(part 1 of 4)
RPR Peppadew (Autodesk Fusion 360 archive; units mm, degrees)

design "servo flipper v2" references "RPR 2A5V Booster", "Flysky FS-iA6 Receiver"
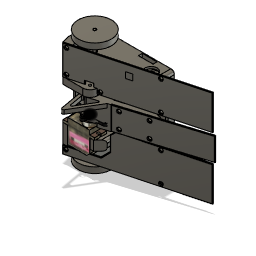
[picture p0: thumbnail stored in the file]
parameter "TrayGap" = 0.2
parameter "TraySideWidth" = 3
parameter "TrayEndExtraMinus1" = 0.8 (= "1 mm - TrayGap")
parameter "d525" = 1
parameter "d1064" = 6.3053
parameter "d551" = -47.5
parameter "d552" = 0
parameter "d553" = -47.5
parameter "d554" = 0
parameter "d555" = -19.75
parameter "d556" = 0
parameter "d557" = -19.75
parameter "d558" = 0
parameter "d559" = 5
parameter "d560" = 0
parameter "d561" = 3
parameter "d562" = 0
parameter "d563" = -8
parameter "d564" = 0
parameter "d565" = -4
parameter "d566" = 0
parameter "d567" = 0.3
parameter "d570" = 0.5
parameter "d571" = 0
parameter "d572" = 0.5
parameter "d573" = 0
parameter "d576" = 80
parameter "d577" = 0
parameter "d578" = 13
parameter "d579" = 0
parameter "d580" = 80
parameter "d581" = 0
parameter "d582" = 13
parameter "d583" = 0
parameter "d584" = 0.001
parameter "d585" = 0
parameter "d588" = -0.001
parameter "d589" = 0
parameter "d590" = 0.283
parameter "d591" = 0
parameter "d592" = -3.999
parameter "d593" = 0
parameter "d595" = 30
parameter "d597" = 30
parameter "d603" = 39.501
parameter "d604" = 0
parameter "d606" = 10
parameter "d607" = 0.5
parameter "d608" = 45
parameter "d611" = -47.5
parameter "d612" = 0
parameter "d613" = -47.5
parameter "d614" = 0
parameter "d615" = 1
parameter "d616" = 0
parameter "d618" = 2
parameter "d619" = 0
parameter "d622" = 2
parameter "d627" = -4
parameter "d628" = 0
parameter "d629" = -3.999
parameter "d630" = 0
place_component Diameter Dimension-2 3.2 Radial Dimension-2 1 Diameter Dimension-2 3.2 Diameter Dimension-3 3.2 Diameter Dimension-2 3 Diameter Dimension-3 7 Diameter Dimension-4 3 Diameter Dimension-5 7 Linear Dimension-2 -3 Linear Dimension-2 1 Linear Dimension-3 45 Linear Dimension-2 -2 Diameter Dimension-2 4 Diameter Dimension-3 4 Radial Dimension-2 4 Linear Dimension-2 10 Linear Dimension-3 15
base_feature "Base Feature1"
base_feature "Base Feature1"
joint "Assemble2" alignAngle -180 alignOffsetX 0 alignOffsetY 0 alignOffsetZ 0 TaperAngle 0
sketch "Sketch2" plane through (0, 6.1985, 0) normal (0, 1, 0) x axis (-1, 0, 0)
  curve K1 (0, 1.25) -> (-1, 0.7813)
  line L1 (-1, -0.8816) -> (-1, 0.7813)
  curve K2 (-1, -0.8816) -> (0, -1.3507)
  curve K3 (0, -1.3507) -> (0, 1.25)
  line L2 (-13.7, -73.6015) -> (-13.7, -30.0015)
  line L3 (-9, -73.6015) -> (-13.7, -73.6015)
  line L4 (-9, -39.8015) -> (-9, -73.6015)
  line L5 (14.2, -39.8015) -> (-9, -39.8015)
  line L6 (14.2, -33.0015) -> (14.2, -39.8015)
  line L7 (-9, -33.0015) -> (14.2, -33.0015)
  line L8 (-9, -30.0015) -> (-9, -33.0015)
  line L9 (-13.7, -30.0015) -> (-9, -30.0015)
  line L10 (-13.7, -39.8015) -> (14.2, -39.8015)
  line L11 (-13.7, -30.0015) -> (-13.7, -39.8015)
  line L12 (14.2, -30.0015) -> (-13.7, -30.0015)
  line L13 (14.2, -39.8015) -> (14.2, -30.0015)
  circle C1 centre (0, 0) radius 17
  circle C2 centre (0, 0) radius 1.5
  point P1 (0, 0)
  point P2 (0, 0)
  coincident P1 P2
  concentric C1 C2
  dimension "d12" diameter C1 = 34
  dimension "d13" diameter C2 = 3
extrude "Extrude2" new body sketch "Sketch2" profile of C1 C2 against normal blind 6
extrude "Extrude3" cut of existing geometry blind -0.25
extrude "Extrude4" cut of existing geometry blind -0.25
offset_faces "OffsetFaces1" distance -0.5
sketch "Sketch3" plane through (0, -3.0015, 0) normal (0, 1, 0) x axis (-1, 0, 0)
  line L1 (6.05, -5.05) -> (6.05, 5)
  line L2 (-6.05, -5.05) -> (6.05, -5.05)
  line L3 (-6.05, 5) -> (-6.05, -5.05)
  line L4 (-9, 5) -> (-6.05, 5)
  line L5 (-9, -8) -> (-9, 5)
  line L6 (9, -8) -> (-9, -8)
  line L7 (9, 5) -> (9, -8)
  line L8 (6.05, 5) -> (9, 5)
  curve K1 (0, 1.25) -> (-1, 0.7813)
  line L9 (-1, -0.8816) -> (-1, 0.7813)
  curve K2 (-1, -0.8816) -> (0, -1.3507)
  curve K3 (0, -1.3507) -> (0, 1.25)
  line L10 (-3, 6.4529) -> (3, 6.4529)
  line L11 (-3, -6.4529) -> (-3, 6.4529)
  line L12 (3, -6.4529) -> (-3, -6.4529)
  line L13 (3, 6.4529) -> (3, -6.4529)
  line L14 (-3, -6.4529) -> (3, 6.4529)
  line L15 (3, -6.4529) -> (-3, 6.4529)
  line L16 (9, 5) -> (-9, 5)
  line L17 (9, -8) -> (9, 5)
  line L18 (-9, -8) -> (9, -8)
  line L19 (-9, 5) -> (-9, -8)
  circle C1 centre (0, 0) radius 3
  point P1 (0, 0)
  point P14 (0, 0)
  point P19 (0, 0)
  point P8 (9, -8)
  point P22 (9, -8)
  point P6 (-9, 5)
  point P20 (-9, 5)
  point P17 (-3, -6.4529)
  point P18 (3, -6.4529)
  coincident P1 P14
  horizontal L10
  perpendicular L10 L11
  parallel L10 L12
  parallel L11 L13
  coincident L14 P19
  coincident L15 P19
  coincident P1 P19
  horizontal L16
  vertical L17
  horizontal L18
  vertical L19
  coincident P8 P22
  coincident P6 P20
  dimension "d21" diameter C1 = 6
  dimension "d22" distance P17 P18 = 6
extrude "Extrude5" add sketch "Sketch3" profile of L1 L2 L3 L4 L5 L6 L7 L8 C1 L11 L12 L13 L16 L17 L18 L19 along normal blind 0.8
base_feature "Base Feature1" AlongDistance -0.001 TaperAngle 0
place_component sketch "Sketch163"
base_feature "Base Feature1" sketch "Sketch163"
joint "Assemble2" alignAngle -180 named "d8_1" alignOffsetX 0 named "d9_1" alignOffsetY 0 named "d10_1" alignOffsetZ 0 named "d11_1"
sketch "Sketch2" plane through (0, 6.1985, 0) normal (0, 1, 0) x axis (-1, 0, 0)
  curve K1 (0, 1.25) -> (-1, 0.7813)
  line L1 (-1, -0.8816) -> (-1, 0.7813)
  curve K2 (-1, -0.8816) -> (0, -1.3507)
  curve K3 (0, -1.3507) -> (0, 1.25)
  circle C1 centre (0, 0) radius 17
  circle C2 centre (0, 0) radius 1.5
  point P1 (0, 0)
  point P2 (0, 0)
  coincident P1 P2
  concentric C1 C2
  dimension "d12_1" diameter C1 = 34
  dimension "d13_1" diameter C2 = 3
extrude "Extrude2" new body sketch "Sketch2" profile of C1 C2 against normal blind 6 named "d14_1"
extrude "Extrude3" cut of existing geometry blind -0.25 named "d16_1"
extrude "Extrude4" cut of existing geometry blind -0.25 named "d18_1"
offset_faces "OffsetFaces1" distance -0.5 named "d20_1"
sketch "Sketch3" plane through (0, -3.0015, 0) normal (0, 1, 0) x axis (-1, 0, 0)
  line L1 (6.05, -5.05) -> (6.05, 5)
  line L2 (-6.05, -5.05) -> (6.05, -5.05)
  line L3 (-6.05, 5) -> (-6.05, -5.05)
  line L4 (-9, 5) -> (-6.05, 5)
  line L5 (-9, -8) -> (-9, 5)
  line L6 (9, -8) -> (-9, -8)
  line L7 (9, 5) -> (9, -8)
  line L8 (6.05, 5) -> (9, 5)
  curve K1 (0, 1.25) -> (-1, 0.7813)
  line L9 (-1, -0.8816) -> (-1, 0.7813)
  curve K2 (-1, -0.8816) -> (0, -1.3507)
  curve K3 (0, -1.3507) -> (0, 1.25)
  line L10 (-3, 6.4529) -> (3, 6.4529)
  line L11 (-3, -6.4529) -> (-3, 6.4529)
  line L12 (3, -6.4529) -> (-3, -6.4529)
  line L13 (3, 6.4529) -> (3, -6.4529)
  line L14 (-3, -6.4529) -> (3, 6.4529)
  line L15 (3, -6.4529) -> (-3, 6.4529)
  line L16 (9, 5) -> (-9, 5)
  line L17 (9, -8) -> (9, 5)
  line L18 (-9, -8) -> (9, -8)
  line L19 (-9, 5) -> (-9, -8)
  circle C1 centre (0, 0) radius 3
  point P1 (0, 0)
  point P14 (0, 0)
  point P19 (0, 0)
  point P8 (9, -8)
  point P22 (9, -8)
  point P6 (-9, 5)
  point P20 (-9, 5)
  point P17 (-3, -6.4529)
  point P18 (3, -6.4529)
  coincident P1 P14
  horizontal L10
  perpendicular L10 L11
  parallel L10 L12
  parallel L11 L13
  coincident L14 P19
  coincident L15 P19
  coincident P1 P19
  horizontal L16
  vertical L17
  horizontal L18
  vertical L19
  coincident P8 P22
  coincident P6 P20
  dimension "d21_1" diameter C1 = 6
  dimension "d22_1" distance P17 P18 = 6
extrude "Extrude5" add sketch "Sketch3" profile of L1 L2 L3 L4 L5 L6 L7 L8 C1 L11 L12 L13 L16 L17 L18 L19 along normal blind 0.8 named "d23_1"
joint "Assemble1" alignAngle 180 alignOffsetX 0 alignOffsetY 0 alignOffsetZ 40
sketch "Shaft" plane through (0, 0, 0) normal (0, 1, 0) x axis (1, 0, 0)
  line L1 (0, 2.4) -> (0, 0)
  line L2 (-0.7416, 2.2825) -> (0, 0)
  line L3 (0, 2.25) -> (-0.6953, 2.1399)
  line L4 (-0.3754, 2.3705) -> (-0.3476, 2.1949)
  line L5 (-4, 2.4) -> (0, 2.4)
  line L6 (-1.5372, 2.0346) -> (-0.352, 2.2223)
  curve K1 (-0.352, 2.2223) -> (0, 2.4)
  curve K2 (-0.0471, 2.4) -> (0.0471, 2.4)
  curve K3 (-0.3985, 2.2149) -> (-0.3054, 2.2297)
  curve K4 (0.352, 2.2223) -> (0, 2.4)
  curve K5 (0.0471, 2.4) -> (-0.0471, 2.4)
  curve K6 (0.3985, 2.2149) -> (0.3054, 2.2297)
  line L7 (0, 0) -> (0.352, 2.2223)
  line L8 (0, 0) -> (-0.352, 2.2223)
  curve K7 (-0.352, 2.2223) -> (-0.7416, 2.2825)
  curve K8 (-0.6968, 2.2971) -> (-0.7865, 2.268)
  curve K9 (-0.3054, 2.2297) -> (-0.3985, 2.2149)
  circle C1 centre (0, 0) radius 1
  circle C2 centre (0, 0) radius 2.4
  circle C3 centre (0, 0) radius 2.25
  circle C4 centre (0, 0) radius 1.625
  point P1 (0, 0)
  point P2 (0, 0)
  point P5 (0, 0)
  point P6 (0, 2.4)
  point P11 (0, 0)
  point P7 (-0.7416, 2.2825)
  point P12 (-0.7416, 2.2825)
  point P13 (-0.6953, 2.1399)
  point P14 (0, 2.25)
  point P15 (-0.3476, 2.1949)
  point P31 (-0.3476, 2.1949)
  point P32 (-0.3754, 2.3705)
  point P34 (-0.352, 2.2223)
  point P40 (0, 2.4)
  point P41 (0.352, 2.2223)
  point P36 (0.0471, 2.4)
  point P42 (-0.0471, 2.4)
  point P37 (-0.0471, 2.4)
  point P43 (0.0471, 2.4)
  point P38 (-0.3054, 2.2297)
  point P44 (0.3054, 2.2297)
  point P39 (-0.3985, 2.2149)
  point P45 (0.3985, 2.2149)
  point P4 (0, 0)
  point P46 (0, 0)
  point P48 (-0.7416, 2.2825)
  point P49 (-0.352, 2.2223)
  point P50 (-0.7865, 2.268)
  point P51 (-0.6968, 2.2971)
  point P52 (-0.3985, 2.2149)
  point P53 (-0.3054, 2.2297)
  point P33 (-4, 2.4)
  point P35 (-1.5372, 2.0346)
  coincident P1 P2
  concentric C1 C2
  concentric C1 C3
  coincident P1 P5
  coincident C2 P6
  vertical L1
  coincident P2 P11
  coincident P7 P12
  coincident C3 P13
  coincident L2 P13
  coincident C3 P14
  coincident L1 P14
  midpoint L3 P15
  coincident P15 P31
  coincident C2 P32
  perpendicular L3 L4
  tangent C2 L5
  coincident C3 P34
  coincident L4 P34
  perpendicular L4 L6
  midpoint P6 K2
  parallel L5 K2
  midpoint P34 K3
  parallel L6 K3
  symmetric P6 L1 P40
  symmetric L1 P34 P41
  symmetric L1 P36 P42
  symmetric L1 P37 P43
  symmetric L1 P38 P44
  symmetric L1 P39 P45
  coincident P4 P46
  concentric C2 C4
  symmetric P6 L4 P48
  symmetric L4 P34 P49
  symmetric L4 P36 P50
  symmetric L4 P37 P51
  symmetric L4 P38 P52
  symmetric L4 P39 P53
  dimension "ScrewholeDia" diameter C1 = 2
  dimension "ShaftOuterDia" diameter C2 = 4.8
  dimension "ShaftSplinesInnerDia" diameter C3 = 4.5
  dimension "d6" distance P6 P33 = 4
  dimension "d7" distance P34 P35 = 1.2 (= "ShaftOuterDia / 4")
  dimension "SplineTipPointiness" distance P36 P37 = 0.0942 (= "ShaftOuterDia * PI / NumSplines / 8")
  dimension "SplineInnerPointiness" distance P38 P39 = 0.0942 (= "ShaftOuterDia * PI / NumSplines / 8")
  dimension "d13_2" diameter C4 = 3.25 (= "ScrewholeDia + 0.5 * ( ( ShaftSplinesInnerDia - ScrewholeDia ) )")
  dimension "d5" C-Pattern1-Angle = 360
  dimension "ServoTrayThickness" AlongDistance = 3
extrude "Extrude3" new body sketch "Shaft" profile of C1 C2 K1 K4 L7 L8 C4 no distance stored bodies "Shaft"
extrude "Extrude4" cut sketch "Shaft" profile of C1 C2 K1 L7 L8 K7 no distance stored
circular_pattern "C-Pattern3" TotalAngle 360
extrude "Extrude1" new body sketch "Shaft" profile of C1 K1 K4 L7 L8 C4 along normal blind 3.5 named "ShaftHeight" bodies "Ignore"
coil_primitive "CoilPrimitive1" Diameter 2 (= "ScrewholeDia") SectionSize 0.2 named "ShaftScrewSectionsize" TaperAngle 0 Revolutions 8.75 (= "ShaftHeight / 0.4 mm") named "ShaftScrewPitch"
extrude "Extrude5" new body sketch "Shaft" profile of C1 L7 L8 no distance stored bodies "Thread"
combine "Combine2"
sketch "Hat" plane through (0, -3.5, 0) normal (0, -1, 0) x axis (1, 0, 0)
  curve K1 (0.352, -2.2223) -> (0, -2.4)
  curve K2 (0.7416, -2.2825) -> (0.352, -2.2223)
  curve K3 (1.0215, -2.0048) -> (0.7416, -2.2825)
  curve K4 (1.4107, -1.9416) -> (1.0215, -2.0048)
  curve K5 (1.591, -1.591) -> (1.4107, -1.9416)
  curve K6 (1.9416, -1.4107) -> (1.591, -1.591)
  curve K7 (2.0048, -1.0215) -> (1.9416, -1.4107)
  curve K8 (2.2825, -0.7416) -> (2.0048, -1.0215)
  curve K9 (2.2223, -0.352) -> (2.2825, -0.7416)
  curve K10 (2.4, 0) -> (2.2223, -0.352)
  curve K11 (2.2223, 0.352) -> (2.4, 0)
  curve K12 (2.2825, 0.7416) -> (2.2223, 0.352)
  curve K13 (2.0048, 1.0215) -> (2.2825, 0.7416)
  curve K14 (1.9416, 1.4107) -> (2.0048, 1.0215)
  curve K15 (1.591, 1.591) -> (1.9416, 1.4107)
  curve K16 (1.4107, 1.9416) -> (1.591, 1.591)
  curve K17 (1.0215, 2.0048) -> (1.4107, 1.9416)
  curve K18 (0.7416, 2.2825) -> (1.0215, 2.0048)
  curve K19 (0.352, 2.2223) -> (0.7416, 2.2825)
  curve K20 (0, 2.4) -> (0.352, 2.2223)
  curve K21 (-0.352, 2.2223) -> (0, 2.4)
  curve K22 (-0.7416, 2.2825) -> (-0.352, 2.2223)
  curve K23 (-1.0215, 2.0048) -> (-0.7416, 2.2825)
  curve K24 (-1.4107, 1.9416) -> (-1.0215, 2.0048)
  curve K25 (-1.591, 1.591) -> (-1.4107, 1.9416)
  curve K26 (-1.9416, 1.4107) -> (-1.591, 1.591)
  curve K27 (-2.0048, 1.0215) -> (-1.9416, 1.4107)
  curve K28 (-2.2825, 0.7416) -> (-2.0048, 1.0215)
  curve K29 (-2.2223, 0.352) -> (-2.2825, 0.7416)
  curve K30 (-2.4, 0) -> (-2.2223, 0.352)
  curve K31 (-2.2223, -0.352) -> (-2.4, 0)
  curve K32 (-2.2825, -0.7416) -> (-2.2223, -0.352)
  curve K33 (-2.0048, -1.0215) -> (-2.2825, -0.7416)
  curve K34 (-1.9416, -1.4107) -> (-2.0048, -1.0215)
  curve K35 (-1.591, -1.591) -> (-1.9416, -1.4107)
  curve K36 (-1.4107, -1.9416) -> (-1.591, -1.591)
  curve K37 (-1.0215, -2.0048) -> (-1.4107, -1.9416)
  curve K38 (-0.7416, -2.2825) -> (-1.0215, -2.0048)
  curve K39 (-0.352, -2.2223) -> (-0.7416, -2.2825)
  curve K40 (0, -2.4) -> (-0.352, -2.2223)
  line L1 (-5.75, 0) -> (0, 0)
  line L2 (8.75, 0) -> (-5.75, 0)
  line L3 (6, 0) -> (8.75, 0)
  circle C1 centre (0, 0) radius 1
  circle C2 centre (0, 0) radius 5.75
  circle C3 centre (6, 0) radius 2.75
  point P2 (0, 0)
  point P45 (0, 0)
  point P46 (-5.75, 0)
  point P48 (6, 0)
  point P49 (6, 0)
  point P47 (8.75, 0)
  concentric C1 C2
  coincident P2 P45
  coincident C2 P46
  horizontal L1
  parallel L1 L2
  parallel L2 L3
  coincident P48 P49
  dimension "HatDia" diameter C2 = 11.5
  dimension "HatTipDia" diameter C3 = 5.5
  dimension "d36" distance P47 P49 = 2.75 (= "HatTipDia / 2")
extrude "Extrude1" new body sketch "Hat" profile of C1 K1 K2 K3 K4 K5 K6 K7 K8 K9 K10 K11 K12 K13 K14 K15 K16 K17 K18 K19 K20 K21 K22 K23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 along normal blind 4.5 named "HatHeight"
sketch "ServoBody" plane through (0, -8, 0) normal (0, -1, 0) x axis (1, 0, 0)
  line L1 (-5.75, 0) -> (0, 0)
  line L2 (16.65, 0) -> (-5.75, 0)
  line L3 (16.65, 12.4) -> (16.65, 0)
  line L4 (-5.75, 6.2) -> (16.65, 6.2)
  line L5 (-5.75, 0) -> (-5.75, 6.2)
  line L6 (16.65, -12.4) -> (16.65, 0)
  line L7 (-5.75, -6.2) -> (16.65, -6.2)
  line L8 (-5.75, 0) -> (-5.75, -6.2)
  circle C1 centre (0, 0) radius 1
  arc A1 centre (6, 0) radius 2.75 clockwise from (5.125, 2.6071) to (5.125, -2.6071)
  arc A2 centre (0, 0) radius 5.75 clockwise from (5.125, -2.6071) to (5.125, 2.6071)
  point P6 (0, 0)
  point P7 (0, 0)
  point P11 (16.65, 6.2)
  point P8 (-5.75, 0)
  point P17 (-5.75, 0)
  point P9 (16.65, 0)
  point P13 (16.65, 0)
  point P10 (16.65, 12.4)
  point P14 (16.65, -12.4)
  point P15 (16.65, -6.2)
  point P12 (-5.75, 6.2)
  point P16 (-5.75, -6.2)
  coincident P6 P7
  horizontal L1
  parallel L1 L2
  perpendicular L2 L3
  midpoint L3 P11
  perpendicular L3 L4
  perpendicular L2 L5
  symmetric P8 L2 P17
  symmetric P9 L2 P13
  symmetric L2 P10 P14
  symmetric L2 P11 P15
  symmetric L2 P12 P16
  dimension "Hole_to_closest_end_dist" distance P7 P8 = 5.75 (= "HatDia / 2")
  dimension "ServoBodyLength" distance P8 P9 = 22.4
  dimension "ServoBodyWidth" distance P9 P10 = 12.4
extrude "Extrude2" add sketch "ServoBody" profile of C1 A1 A2 L3 L4 L5 L6 L7 L8 along normal blind 24 named "ServoBodyHeight"
chamfer "Chamfer1" distance 3 named "ServoCornerWireRecess"
work_plane "WorkPlane1" AlongDistance -4.4 named "ServoTabRecess"
sketch "ScrewTab" plane through (5.45, -12.4, 0) normal (0, 1, 0) x axis (1, 0, 0)
  line L1 (-11.2, -6.2) -> (11.2, -6.2)
  line L2 (-11.2, 0) -> (-11.2, -6.2)
  line L3 (-11.2, 0) -> (-11.2, 6.2)
  line L4 (-11.2, 6.2) -> (11.2, 6.2)
  line L5 (11.2, 12.4) -> (11.2, 0)
  line L6 (11.2, -12.4) -> (11.2, 0)
  line L7 (11.2, 0) -> (-11.2, 0)
  line L8 (-16.2, -6.2) -> (-11.2, -6.2)
  line L9 (-16.2, 6.2) -> (-16.2, -6.2)
  line L10 (-11.2, 6.2) -> (-16.2, 6.2)
  line L11 (-11.2, -6.2) -> (-11.2, 6.2)
  line L12 (16.2, -6.2) -> (11.2, -6.2)
  line L13 (16.2, 6.2) -> (16.2, -6.2)
  line L14 (11.2, 6.2) -> (16.2, 6.2)
  line L15 (11.2, -6.2) -> (11.2, 6.2)
  line L16 (12.6, 0) -> (16.2, 0)
  line L17 (13.9, 0) -> (12.6, 0)
  line L18 (-16.2, 0) -> (16.2, 0)
  line L19 (0, -6.2) -> (0, 0)
  line L20 (13.9, -1.2) -> (13.9, 0)
  line L21 (16.2, -0.6) -> (16.2, -6.2)
  line L22 (15.0533, -0.6) -> (16.2, -0.6)
  line L23 (15.0533, 0.6) -> (16.2, 0.6)
  line L24 (16.2, 0.6) -> (16.2, 6.2)
  line L25 (-15.0533, 0.6) -> (-16.2, 0.6)
  line L26 (-15.0533, -0.6) -> (-16.2, -0.6)
  line L27 (-16.2, -0.6) -> (-16.2, -6.2)
  line L28 (-16.2, 0.6) -> (-16.2, 6.2)
  circle C1 centre (13.9, 0) radius 1.3
  circle C2 centre (-13.9, 0) radius 1.3
  point P4 (-11.2, -6.2)
  point P16 (-11.2, -6.2)
  point P2 (11.2, -6.2)
  point P20 (11.2, -6.2)
  point P24 (16.2, 0)
  point P26 (13.9, 0)
  point P27 (13.9, 0)
  point P28 (-16.2, 0)
  point P29 (0, 0)
  point P31 (13.9, 0)
  point P34 (15.0533, -0.6)
  point P21 (16.2, -6.2)
  point P37 (16.2, 6.2)
  point P33 (16.2, -0.6)
  point P35 (16.2, 0.6)
  point P36 (15.0533, 0.6)
  point P43 (-16.2, -6.2)
  point P41 (-16.2, -0.6)
  point P42 (-15.0533, -0.6)
  point P39 (-16.2, 0.6)
  point P40 (-15.0533, 0.6)
  point P44 (-16.2, 6.2)
  point P17 (-16.2, -6.2)
  point P19 (-11.2, 6.2)
  point P23 (11.2, 6.2)
  point P25 (12.6, 0)
  point P30 (0, -6.2)
  point P32 (13.9, -1.2)
  horizontal L8
  vertical L9
  horizontal L10
  vertical L11
  coincident P4 P16
  horizontal L12
  vertical L13
  horizontal L14
  vertical L15
  coincident P2 P20
  midpoint L13 P24
  perpendicular L13 L16
  perpendicular L13 L17
  coincident P26 P27
  midpoint L9 P28
  coincident L7 P29
  perpendicular L7 L19
  midpoint L18 P29
  coincident P26 P31
  perpendicular L18 L20
  perpendicular L12 L21
  coincident C1 P34
  perpendicular L21 L22
  symmetric P21 L16 P37
  symmetric L16 P33 P35
  symmetric L16 P34 P36
  symmetric P21 L19 P43
  symmetric C1 L19 C2
  symmetric L19 P33 P41
  symmetric L19 P34 P42
  symmetric L19 P35 P39
  symmetric L19 P36 P40
  symmetric L19 P37 P44
  dimension "ServoTabSize" distance P16 P17 = 5
  dimension "d47" distance P16 P19 = 12.4 (= "ServoBodyWidth")
  dimension "d48" distance P20 P21 = 5 (= "ServoTabSize")
  dimension "d49" distance P20 P23 = 12.4 (= "ServoBodyWidth")
  dimension "ServoHoleRecess" distance P24 P25 = 3.6
  dimension "TabScrewSize" diameter C1 = 2.6
  dimension "d52" distance P25 P27 = 1.3 (= "TabScrewSize / 2")
  dimension "d53" distance P29 P30 = 6.2 (= "ServoBodyWidth / 2")
  dimension "TabScrewGapSize" distance P31 P32 = 1.2
  dimension "d55" distance P21 P33 = 5.6 (= "( ServoBodyWidth - TabScrewGapSize ) / 2")
extrude "Extrude3" add sketch "ScrewTab" profile of L2 L3 L5 L6 L8 L10 L11 L12 L14 L15 C1 L21 L22 L23 L24 C2 L25 L26 L27 L28 against normal blind 2.4 named "TabThickness"
sketch "WireHole" plane through (-17.375, -17.375, 0) normal (-0.7071, -0.7071, 0) x axis (0, 0, 1)
  line L1 (-6.2, -20.6829) -> (-6.2, -16.4402)
  line L2 (6.2, -20.6829) -> (-6.2, -20.6829)
  line L3 (6.2, -16.4402) -> (6.2, -20.6829)
  line L4 (-6.2, -16.4402) -> (6.2, -16.4402)
  line L5 (-6.2, -16.4402) -> (6.2, -16.4402)
  line L6 (6.2, -20.6829) -> (-6.2, -20.6829)
  line L7 (9.2, -20.6829) -> (6.2, -20.6829)
  line L8 (9.2, -20.2829) -> (9.2, -20.6829)
  line L9 (9.2, -18.2829) -> (9.2, -20.2829)
  line L10 (0, -18.2829) -> (0, -20.2829)
  line L11 (-1.5, -18.2829) -> (0, -18.2829)
  line L12 (1.5, -18.2829) -> (-1.5, -18.2829)
  line L13 (1.5, -20.2829) -> (1.5, -18.2829)
  line L14 (-1.5, -20.2829) -> (1.5, -20.2829)
  line L15 (-1.5, -18.2829) -> (-1.5, -20.2829)
  line L16 (-1.5, -19.2829) -> (1.5, -19.2829)
  line L17 (-0.85, -19.2829) -> (0, -19.2829)
  circle C1 centre (0, -19.2829) radius 0.375
  circle C2 centre (-0.85, -19.2829) radius 0.375
  circle C3 centre (0.85, -19.2829) radius 0.375
  point P4 (6.2, -20.6829)
  point P10 (6.2, -20.6829)
  point P20 (1.5, -19.2829)
  point P21 (-1.5, -19.2829)
  point P22 (0, -19.2829)
  point P23 (0, -19.2829)
  point P24 (-0.85, -19.2829)
  point P25 (-0.85, -19.2829)
  point P11 (9.2, -20.6829)
  point P12 (9.2, -20.2829)
  point P13 (9.2, -18.2829)
  point P14 (0, -20.2829)
  point P15 (0, -18.2829)
  point P16 (-1.5, -18.2829)
  point P17 (1.5, -18.2829)
  point P19 (-1.5, -20.2829)
  coincident P4 P10
  perpendicular L3 L7
  perpendicular L7 L8
  parallel L8 L9
  perpendicular L2 L10
  perpendicular L10 L11
  horizontal L12
  vertical L13
  horizontal L14
  vertical L15
  midpoint L13 P20
  midpoint L15 P21
  midpoint L10 P22
  coincident P22 P23
  perpendicular L10 L17
  coincident P24 P25
  symmetric L10 C2 C3
  dimension "WireHoleWidth" distance P10 P11 = 3
  dimension "WireHoleOffset" distance P11 P12 = 0.4
  dimension "WireHoleHeight" distance P12 P13 = 2
  dimension "d61" distance P14 P15 = 2 (= "WireHoleHeight")
  dimension "d62" distance P15 P16 = 1.5 (= "WireHoleWidth / 2")
  dimension "d63" distance P16 P17 = 3 (= "WireHoleWidth")
  dimension "d64" distance P16 P19 = 2 (= "WireHoleHeight")
  dimension "d65" diameter C1 = 0.75 (= "WireHoleWidth / 4")
  dimension "d66" distance P23 P24 = 0.85 (= "WireHoleWidth / 4 + 0.1 mm")
  dimension "d67" diameter C2 = 0.75 (= "WireHoleWidth / 4")
extrude "Extrude4" cut sketch "WireHole" profile of L11 L12 L13 L14 L15 C1 C2 C3 no distance stored
extrude "Extrude5" new body sketch "WireHole" profile of C1 C2 C3 along normal blind 5 named "WireLenght" bodies "Signal", "Positive", "Ground"
sketch "Horn" plane through (0, 0, 0) normal (0, 1, 0) x axis (1, 0, 0)
  curve K1 (0, 2.4) -> (0.352, 2.2223)
  curve K2 (-0.352, 2.2223) -> (0, 2.4)
  curve K3 (-0.7416, 2.2825) -> (-0.352, 2.2223)
  curve K4 (-1.0215, 2.0048) -> (-0.7416, 2.2825)
  curve K5 (-1.4107, 1.9416) -> (-1.0215, 2.0048)
  curve K6 (-1.591, 1.591) -> (-1.4107, 1.9416)
  curve K7 (-1.9416, 1.4107) -> (-1.591, 1.591)
  curve K8 (-2.0048, 1.0215) -> (-1.9416, 1.4107)
  curve K9 (-2.2825, 0.7416) -> (-2.0048, 1.0215)
  curve K10 (-2.2223, 0.352) -> (-2.2825, 0.7416)
  curve K11 (-2.4, 0) -> (-2.2223, 0.352)
  curve K12 (-2.2223, -0.352) -> (-2.4, 0)
  curve K13 (-2.2825, -0.7416) -> (-2.2223, -0.352)
  curve K14 (-2.0048, -1.0215) -> (-2.2825, -0.7416)
  curve K15 (-1.9416, -1.4107) -> (-2.0048, -1.0215)
  curve K16 (-1.591, -1.591) -> (-1.9416, -1.4107)
  curve K17 (-1.4107, -1.9416) -> (-1.591, -1.591)
  curve K18 (-1.0215, -2.0048) -> (-1.4107, -1.9416)
  curve K19 (-0.7416, -2.2825) -> (-1.0215, -2.0048)
  curve K20 (-0.352, -2.2223) -> (-0.7416, -2.2825)
  curve K21 (0, -2.4) -> (-0.352, -2.2223)
  curve K22 (0.352, -2.2223) -> (0, -2.4)
  curve K23 (0.7416, -2.2825) -> (0.352, -2.2223)
  curve K24 (1.0215, -2.0048) -> (0.7416, -2.2825)
  curve K25 (1.4107, -1.9416) -> (1.0215, -2.0048)
  curve K26 (1.591, -1.591) -> (1.4107, -1.9416)
  curve K27 (1.9416, -1.4107) -> (1.591, -1.591)
  curve K28 (2.0048, -1.0215) -> (1.9416, -1.4107)
  curve K29 (2.2825, -0.7416) -> (2.0048, -1.0215)
  curve K30 (2.2223, -0.352) -> (2.2825, -0.7416)
  curve K31 (2.4, 0) -> (2.2223, -0.352)
  curve K32 (2.2223, 0.352) -> (2.4, 0)
  curve K33 (2.2825, 0.7416) -> (2.2223, 0.352)
  curve K34 (2.0048, 1.0215) -> (2.2825, 0.7416)
  curve K35 (1.9416, 1.4107) -> (2.0048, 1.0215)
  curve K36 (1.591, 1.591) -> (1.9416, 1.4107)
  curve K37 (1.4107, 1.9416) -> (1.591, 1.591)
  curve K38 (1.0215, 2.0048) -> (1.4107, 1.9416)
  curve K39 (0.7416, 2.2825) -> (1.0215, 2.0048)
  curve K40 (0.352, 2.2223) -> (0.7416, 2.2825)
  line L1 (18.3, -9.7) -> (18.3, 9.7)
  line L2 (0.2838, -3.8395) -> (15.799, -2.6927)
  line L3 (3.7433, 0.9) -> (4.9, 0.9)
  line L4 (-18.3, -9.7) -> (18.3, -9.7)
  line L5 (-0.2838, -3.8395) -> (-15.799, -2.6927)
  line L6 (-0.2838, 3.8395) -> (-15.799, 2.6927)
  line L7 (-4.9, 0.9) -> (-4.9, 0)
  line L8 (4.9, -4.05) -> (-4.9, -4.05)
  line L9 (-3.1395, -2.2284) -> (-4.9, -2.0983)
  line L10 (-4.9, -4.05) -> (-4.9, 4.05)
  line L11 (-18.3, 0) -> (0, 0)
  line L12 (-3.7433, -0.9) -> (-4.9, -0.9)
  line L13 (-18.3, 9.7) -> (-18.3, -9.7)
  line L14 (-16.2, 0) -> (-15.6, 0)
  line L15 (-2.2, -7.5) -> (-2.2, 7.5)
  line L16 (-3.7433, 0.9) -> (-4.9, 0.9)
  line L17 (0, 9.7) -> (0, 0)
  line L18 (4.9, 4.05) -> (-4.9, -4.05)
  line L19 (-18.3, -9.7) -> (18.3, 9.7)
  line L20 (-3.1395, 2.2284) -> (-4.9, 2.0983)
  line L21 (0, 7.75) -> (0, 7.5)
  line L22 (-4.9, 4.05) -> (4.9, -4.05)
  line L23 (4.9, 2.0983) -> (4.9, 3.4983)
  line L24 (18.3, -9.7) -> (-18.3, 9.7)
  line L25 (4.9, 4.05) -> (4.9, -4.05)
  line L26 (3.1395, -2.2284) -> (4.9, -2.0983)
  line L27 (-4.9, 4.05) -> (4.9, 4.05)
  line L28 (2.2, -7.5) -> (2.2, 7.5)
  line L29 (0.2838, 3.8395) -> (15.799, 2.6927)
  line L30 (3.1395, 2.2284) -> (4.9, 2.0983)
  line L31 (3.7433, -0.9) -> (4.9, -0.9)
  line L32 (18.3, 9.7) -> (-18.3, 9.7)
  circle C1 centre (0, 0) radius 1
  circle C2 centre (13.725, 0) radius 1
  circle C3 centre (0, 7.75) radius 1
  circle C4 centre (0, 7.5) radius 2.2
  circle C5 centre (-8.775, 0) radius 1
  circle C6 centre (0, 0) radius 3.85
  circle C7 centre (8.775, 0) radius 1
  circle C8 centre (6.3, 0) radius 1
  circle C9 centre (15.6, 0) radius 2.7
  circle C10 centre (0, 0) radius 1.25
  circle C11 centre (-11.25, 0) radius 1
  circle C12 centre (-16.2, 0) radius 1
  circle C13 centre (-15.6, 0) radius 2.7
  circle C14 centre (-6.3, 0) radius 1
  circle C15 centre (-13.725, 0) radius 1
  circle C16 centre (0, -5.25) radius 1
  circle C17 centre (0, -7.75) radius 1
  circle C18 centre (0, 0) radius 2.325
  circle C19 centre (0, -7.5) radius 2.2
  circle C20 centre (11.25, 0) radius 1
  circle C21 centre (0, 5.25) radius 1
  circle C22 centre (16.2, 0) radius 1
  point P48 (0, 0)
  point P49 (0, 0)
  point P55 (0, 0)
  point P57 (0, 0)
  point P58 (0, 9.7)
  point P59 (0, 0)
  point P60 (-18.3, 0)
  point P56 (-15.6, 0)
  point P61 (0, 7.5)
  point P62 (-15.799, 2.6927)
  point P63 (-0.2838, 3.8395)
  point P65 (-2.2, 7.5)
  point P66 (-2.2, -7.5)
  point P67 (2.2, 7.5)
  point P68 (2.2, -7.5)
  point P69 (-15.799, -2.6927)
  point P70 (-0.2838, -3.8395)
  point P71 (0, 0)
  point P89 (15.799, 2.6927)
  point P90 (0.2838, 3.8395)
  point P87 (15.799, -2.6927)
  point P88 (0.2838, -3.8395)
  point P95 (0, 0)
  point P96 (4.9, 3.4983)
  point P98 (3.1395, 2.2284)
  point P99 (-4.9, 0)
  point P101 (-3.7433, 0.9)
  point P97 (4.9, 2.0983)
  point P104 (4.9, -2.0983)
  point P105 (3.1395, -2.2284)
  point P100 (-4.9, 0.9)
  point P102 (-4.9, -0.9)
  point P103 (-3.7433, -0.9)
  point P112 (-4.9, 2.0983)
  point P113 (-3.1395, 2.2284)
  point P108 (4.9, 0.9)
  point P109 (3.7433, 0.9)
  point P106 (4.9, -0.9)
  point P107 (3.7433, -0.9)
  point P110 (-4.9, -2.0983)
  point P111 (-3.1395, -2.2284)
  point P45 (-15.6, 0)
  point P44 (-16.2, 0)
  point P72 (-16.2, 0)
  point P46 (0, 7.5)
  point P47 (0, 7.75)
  point P77 (0, 7.75)
  point P53 (18.3, -9.7)
  point P54 (-18.3, -9.7)
  point P52 (18.3, 9.7)
  point P93 (4.9, 4.05)
  point P94 (-4.9, 4.05)
  point P92 (4.9, -4.05)
  coincident P48 P49
  concentric C6 C18
  horizontal L32
  perpendicular L1 L32
  parallel L4 L32
  parallel L1 L13
  coincident P55 L24
  coincident P55 L19
  coincident P49 P55
  coincident P55 P57
  midpoint P58 L32
  coincident P48 P59
  midpoint P60 L13
  coincident P60 C13
  coincident P56 L11
  coincident P58 C4
  coincident P61 L17
  coincident P62 C13
  coincident P63 C6
  tangent L6 C13
  tangent C6 L6
  symmetric C4 L11 C19
  coincident P65 C4
  coincident P66 C19
  vertical L15
  tangent C4 L15
  symmetric P65 P67 L17
  symmetric P66 P68 L17
  symmetric P62 P69 L11
  symmetric P63 P70 L11
  coincident P48 P71
  symmetric C3 L11 C17
  symmetric L11 C16 C21
  symmetric C9 L17 C13
  symmetric P62 P89 L17
  symmetric P63 P90 L17
  symmetric P69 P87 L17
  symmetric P70 P88 L17
  symmetric L17 C12 C22
  symmetric C2 L17 C15
  symmetric C11 L17 C20
  symmetric C5 C7 L17
  symmetric C8 L17 C14
  horizontal L8
  perpendicular L8 L25
  parallel L8 L27
  parallel L10 L25
  coincident P95 L18
  coincident P95 L22
  coincident P71 P95
  parallel L23 L25
  coincident P96 L29
  coincident P96 L25
  coincident P98 C6
  parallel L29 L30
  midpoint P99 L10
  perpendicular L7 L11
  coincident P101 C6
  perpendicular L7 L16
  symmetric P97 P104 L11
  symmetric P98 P105 L11
  symmetric P100 P102 L11
  symmetric P101 P103 L11
  symmetric P97 P112 L17
  symmetric P98 P113 L17
  symmetric P100 P108 L17
  symmetric P101 P109 L17
  symmetric P102 P106 L17
  symmetric P103 P107 L17
  symmetric P104 P110 L17
  symmetric P105 P111 L17
  coincident P45 P56
  parallel L11 L14
  coincident P44 P72
  coincident P46 P61
  parallel L17 L21
  coincident P47 P77
  dimension "OuterHubDia" = 0 (= "7.3 mm + 2 * tol")
  dimension "InnerHubDia" diameter C18 = 4.65
  dimension "MajorArmLen" distance P53 P54 = 36.6 (= "36.2 mm + 2 * tol")
  dimension "MinroArmLen" distance P52 P53 = 19.4 (= "19 mm + 2 * tol")
  dimension "TipDiaMajor" = 0 (= "5 mm + 2 * tol")
  dimension "TipDiaMinor" = 0 (= "4 mm + 2 * tol")
  dimension "ScrewHole" diameter C10 = 2.5
  dimension "DriveHole" diameter C12 = 2
  dimension "d14_2" diameter C3 = 2 (= "DriveHole")
  dimension "d19_2" distance P93 P94 = 9.8 (= "OuterHubDia + 1.5 mm + tol + 2 * tol")
  dimension "d90" distance P92 P93 = 8.1 (= "OuterHubDia + 2 * tol")
  dimension "ReinforcerWidth" distance P96 P97 = 1.4 (= "1 mm + 2 * tol")
  dimension "d92" distance P99 P100 = 0.9 (= "ReinforcerWidth / 2 + tol")
  dimension "HoleSlideAdj" distance P44 P45 = 0.6
  dimension "SideHoleSlideAdj" distance P46 P47 = 0.25
  dimension "d74" R-Pattern1-uDistance = 9.9
  dimension "d75" R-Pattern1-vDistance = 0
  dimension "d78" R-Pattern2-uDistance = 0
  dimension "d79" R-Pattern2-vDistance = -2.5
extrude "Extrude1" new body sketch "Horn" profile of K1 K2 K3 K4 K5 K6 K7 K8 K9 K10 K11 K12 K13 K14 K15 K16 K17 K18 K19 K20 K21 K22 K23 K24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 against normal blind 2.7 named "HornCollarDepth" bodies "ServoHorn"
extrude "Extrude2" add sketch "Horn" profile of C2 C3 L2 L3 C4 C5 L5 C6 C7 L6 C8 C9 L7 L9 L10 L12 L15 C11 L16 C12 C13 C14 C15 C16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 against normal blind 1 named "HornUnderside" and along normal blind 1.5 named "HornArmTopSide"
extrude "Extrude3" add sketch "Horn" profile of K1 K2 K3 K4 K5 K6 K7 K8 K9 K10 K11 K12 K13 K14 K15 K16 K17 K18 K19 K20 K21 K22 K23 K24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 along normal blind 1.2 named "HornInnerScrewTabThickness"
extrude "Extrude4" add sketch "Horn" profile of K1 K2 K3 K4 K5 K6 K7 K8 K9 K10 K11 K12 K13 K14 K15 K16 K17 K18 K19 K20 K21 K22 K23 K24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 along normal blind 2.3 named "HornUpperHeight"
chamfer "Chamfer1" distance 0.7667 (= "HornUpperHeight / 3")
ground "Ground1"
sketch "ServoOrigin" plane through (0, 0, 0) normal (0, 1, 0) x axis (-1, 0, 0)
  circle C1 centre (0, 0) radius 1
sketch "Sketch1" plane through (0, 0, 0) normal (0, 1, 0) x axis (-1, 0, 0)
  circle C1 centre (0, 0) radius 1
joint "Assemble1" alignAngle 0 alignOffsetX 0 alignOffsetY 0 alignOffsetZ 0
joint "Assemble2" alignAngle 0 alignOffsetX 0 alignOffsetY 0 alignOffsetZ 0
as_built_joint "As-built1" OffsetX 0 OffsetY 0 OffsetZ 0 AngleZ 0
as_built_joint "As-built2" OffsetX 0 OffsetY 0 OffsetZ 0 AngleZ 0
ground "Ground1"
position "Position1"
joint "Assemble2" alignAngle 0 alignOffsetX -1 alignOffsetY -19 alignOffsetZ -27
sketch "Sketch1" plane through (-9, 5, 0) normal (-1, 0, 0) x axis (0, 0, 1)
  line L1 (5, -95.8015) -> (5, -106.4015)
  line L2 (-2.3714, -95.8015) -> (5, -95.8015)
  line L3 (-2.3714, -92.3015) -> (-2.3714, -95.8015)
  line L4 (-2.3714, -82.8015) -> (-2.3714, -92.3015)
  line L5 (-2.3714, -76.8015) -> (-2.3714, -82.8015)
  line L6 (-8, -76.8015) -> (-2.3714, -76.8015)
  line L7 (-8, -106.4015) -> (-8, -76.8015)
  line L8 (5, -106.4015) -> (-8, -106.4015)
  line L9 (-8, -17.8015) -> (-8, -7.2015)
  line L10 (-2.3714, -17.8015) -> (-8, -17.8015)
  line L11 (5, -17.8015) -> (-2.3714, -17.8015)
  line L12 (5, -7.2015) -> (5, -17.8015)
  line L13 (-8, -7.2015) -> (5, -7.2015)
  line L14 (-8, -17.8015) -> (-2.3714, -17.8015)
  line L15 (-8, -36.8015) -> (-8, -17.8015)
  line L16 (-2.3714, -36.8015) -> (-8, -36.8015)
  line L17 (-2.3714, -30.8015) -> (-2.3714, -36.8015)
  line L18 (-2.3714, -21.3015) -> (-2.3714, -30.8015)
  line L19 (-2.3714, -17.8015) -> (-2.3714, -21.3015)
  line L20 (19, -78.6015) -> (6.6, -78.6015)
  line L21 (19, -92.8015) -> (19, -78.6015)
  line L22 (6.6, -92.8015) -> (19, -92.8015)
  line L23 (6.6, -78.6015) -> (6.6, -92.8015)
  line L24 (6.6, -76.2015) -> (19, -76.2015)
  line L25 (6.6, -71.8015) -> (6.6, -76.2015)
  line L26 (12.8, -71.8015) -> (6.6, -71.8015)
  line L27 (19, -71.8015) -> (12.8, -71.8015)
  line L28 (19, -76.2015) -> (19, -71.8015)
  line L29 (5, -17.8015) -> (-8, -17.8015)
  line L30 (5, -106.4015) -> (5, -17.8015)
  line L31 (-8, -106.4015) -> (5, -106.4015)
  line L32 (-8, -17.8015) -> (-8, -106.4015)
  line L33 (19, -95.8015) -> (6.6, -95.8015)
  point P2 (5, -106.4015)
  point P32 (5, -106.4015)
  point P11 (-8, -17.8015)
  point P30 (-8, -17.8015)
  horizontal L29
  vertical L30
  horizontal L31
  vertical L32
  coincident P2 P32
  coincident P11 P30
extrude "Extrude6" add sketch "Sketch1" profile of L1 L2 L3 L4 L5 L6 L7 L8 L9 L10 L11 L12 L13 L14 L15 L16 L17 L18 L19 L29 L30 L31 L32 along normal blind 3.7
copy_paste_bodies "CutPasteBodies"
combine "Combine1"
sketch "Sketch2" plane through (-12.7, 5, 0) normal (-1, 0, 0) x axis (0, 0, 1)
  line L1 (-8, -7.2015) -> (5, -7.2015)
  line L2 (-8, -106.4015) -> (-8, -7.2015)
  line L3 (5, -106.4015) -> (-8, -106.4015)
  line L4 (5, -7.2015) -> (5, -106.4015)
  line L5 (16, -7.2015) -> (-8, -7.2015)
  line L6 (16, -96.4015) -> (16, -7.2015)
  line L7 (-8, -96.4015) -> (16, -96.4015)
  line L8 (-8, -7.2015) -> (-8, -96.4015)
  line L9 (5.5, -59.8015) -> (5, -59.8015)
  arc A1 centre (4.25, -59.8015) radius 0.25 clockwise from (4, -59.8015) to (4.5, -59.8015)
  point P3 (-8, -7.2015)
  point P7 (-8, -7.2015)
  point P8 (16, -7.2015)
  horizontal L5
  vertical L6
  horizontal L7
  vertical L8
  coincident P3 P7
  dimension "d40" distance P7 P8 = 24
extrude "Extrude7" add sketch "Sketch2" along normal blind 5
sketch "Sketch98" plane through (0, 0, 16) normal (0, 0, 1) x axis (1, 0, 0)
  line L1 (-12.7, -2.2015) -> (-12.7, -91.4015)
  line L2 (-17.7, -2.2015) -> (-12.7, -2.2015)
  line L3 (-17.7, -91.4015) -> (-17.7, -2.2015)
  line L4 (-12.7, -91.4015) -> (-17.7, -91.4015)
extrude "Extrude116" add of existing geometry blind 40
extrude "Extrude117" add of existing geometry blind 5
sketch "Sketch99" plane through (-12.7, 0, 0) normal (-1, 0, 0) x axis (0, 0, 1)
  line L1 (-13, -91.4015) -> (5, -91.4015)
  line L2 (-13, -101.4015) -> (-13, -91.4015)
  line L3 (5, -101.4015) -> (-13, -101.4015)
  line L4 (5, -91.4015) -> (5, -101.4015)
  line L5 (-13, -2.2015) -> (16, -2.2015)
  line L6 (-13, -91.4015) -> (-13, -2.2015)
  line L7 (16, -91.4015) -> (-13, -91.4015)
  line L8 (16, -2.2015) -> (16, -91.4015)
  line L9 (16, -101.4015) -> (-13, -101.4015)
  line L10 (16, -91.4015) -> (16, -101.4015)
  line L11 (-13, -91.4015) -> (16, -91.4015)
  line L12 (-13, -101.4015) -> (-13, -91.4015)
  point P9 (16, -91.4015)
  point P12 (16, -91.4015)
  point P4 (-13, -101.4015)
  point P10 (-13, -101.4015)
  horizontal L9
  vertical L10
  horizontal L11
  vertical L12
  coincident P9 P12
  coincident P4 P10
extrude "Extrude118" add sketch "Sketch99" profile of L1 L2 L3 L4 L7 L9 L10 L11 L12 along normal blind 5
extrude "Extrude119" add of existing geometry blind 40
sketch "Sketch100" plane through (9, 0, 0) normal (1, 0, 0) x axis (0, 0, -1)
  line L1 (8, -90.8015) -> (2.3714, -90.8015)
  line L2 (8, -71.8015) -> (8, -90.8015)
  line L3 (2.3714, -71.8015) -> (8, -71.8015)
  line L4 (2.3714, -77.8015) -> (2.3714, -71.8015)
  line L5 (2.3714, -87.3015) -> (2.3714, -77.8015)
  line L6 (2.3714, -90.8015) -> (2.3714, -87.3015)
sketch "Sketch101" plane through (0, 0, -2.3714) normal (0, 0, 1) x axis (1, 0, 0)
  line L1 (7.467, -12.8015) -> (49, -12.8015)
  line L2 (7.467, -16.3015) -> (7.467, -12.8015)
  line L3 (9, -16.3015) -> (7.467, -16.3015)
  line L4 (9, -25.8015) -> (9, -16.3015)
  line L5 (7.467, -26.0515) -> (7.467, -25.8015)
  line L6 (6.9285, -26.0515) -> (7.467, -26.0515)
  line L7 (6.9285, -71.8015) -> (6.9285, -26.0515)
  line L8 (9, -71.8015) -> (6.9285, -71.8015)
  line L9 (49, -71.8015) -> (9, -71.8015)
  line L10 (49, -12.8015) -> (49, -71.8015)
  line L11 (9, -71.8015) -> (49, -71.8015)
  line L12 (9, -12.8015) -> (9, -71.8015)
  line L13 (49, -12.8015) -> (9, -12.8015)
  line L14 (49, -71.8015) -> (49, -12.8015)
  line L15 (7.467, -25.8015) -> (9, -25.8015)
  point P15 (9, -12.8015)
  point P12 (49, -71.8015)
  point P13 (49, -71.8015)
  horizontal L11
  vertical L12
  horizontal L13
  vertical L14
  coincident L1 P15
  coincident P12 P13
extrude "Extrude121" cut sketch "Sketch101" profile of L1 L3 L9 L10 L11 L12 L13 L14 against normal blind 5.629
extrude "Extrude122" add of existing geometry blind 11
extrude "Extrude123" add of existing geometry blind 3
sketch "Sketch102" plane through (0, 0, 19) normal (0, 0, 1) x axis (1, 0, 0)
  line L1 (-17.7, -2.2015) -> (-3, -2.2015)
  line L2 (-17.7, -101.4015) -> (-17.7, -2.2015)
  line L3 (-3, -101.4015) -> (-17.7, -101.4015)
  line L4 (-3, -100.6015) -> (-3, -101.4015)
  line L5 (-6.05, -100.6015) -> (-3, -100.6015)
  line L6 (-6.05, -90.8015) -> (-6.05, -100.6015)
  line L7 (-9, -90.8015) -> (-6.05, -90.8015)
  line L8 (-9, -12.8015) -> (-9, -90.8015)
  line L9 (-6.05, -12.8015) -> (-9, -12.8015)
  line L10 (-6.05, -3.0015) -> (-6.05, -12.8015)
  line L11 (-3, -3.0015) -> (-6.05, -3.0015)
  line L12 (-3, -2.2015) -> (-3, -3.0015)
  line L13 (13.7, -87.8015) -> (10.7, -90.8015)
  line L14 (13.7, -73.6015) -> (13.7, -87.8015)
  line L15 (18.7, -73.6015) -> (13.7, -73.6015)
  line L16 (18.7, -71.2015) -> (18.7, -73.6015)
  line L17 (13.7, -71.2015) -> (18.7, -71.2015)
  line L18 (13.7, -66.8015) -> (13.7, -71.2015)
  line L19 (-8.7, -66.8015) -> (13.7, -66.8015)
  line L20 (-8.7, -71.2015) -> (-8.7, -66.8015)
  line L21 (-13.7, -71.2015) -> (-8.7, -71.2015)
  line L22 (-13.7, -73.6015) -> (-13.7, -71.2015)
  line L23 (-8.7, -73.6015) -> (-13.7, -73.6015)
  line L24 (-8.7, -90.8015) -> (-8.7, -73.6015)
  line L25 (10.7, -90.8015) -> (-8.7, -90.8015)
  line L26 (-17.7, -73.6015) -> (-8.7, -73.6015)
  line L27 (-17.7, -30.0015) -> (-17.7, -73.6015)
  line L28 (-8.7, -30.0015) -> (-17.7, -30.0015)
  line L29 (-8.7, -73.6015) -> (-8.7, -30.0015)
  point P29 (-17.7, -30.0015)
  point P25 (-8.7, -73.6015)
  point P27 (-8.7, -73.6015)
  point P4 (-17.7, -101.4015)
  point P28 (-17.7, -73.6015)
  horizontal L26
  vertical L27
  horizontal L28
  vertical L29
  coincident L2 P29
  coincident P25 P27
  dimension "d649" distance P4 P28 = 27.8
  dimension "d650" distance L1 L28 = 27.8 (= "d649")
extrude "Extrude124" cut sketch "Sketch102" profile of L2 L8 L21 L22 L23 L26 L27 L28 against normal blind 12.4
extrude "Extrude125" cut of existing geometry blind -4
sketch "Sketch103" plane through (0, 0, 6.6) normal (0, 0, 1) x axis (1, 0, 0)
  line L1 (-13.7, -73.6015) -> (-13.7, -30.0015)
  line L2 (-9, -73.6015) -> (-13.7, -73.6015)
  line L3 (-9, -30.0015) -> (-9, -73.6015)
  line L4 (-13.7, -30.0015) -> (-9, -30.0015)
  line L5 (73.243, -51.8015) -> (-13.7, -51.8015)
  line L6 (73.243, -39.8015) -> (-13.7, -39.8015)
  line L7 (-9, -33.0015) -> (-9, -30.0015)
  line L8 (13.7, -87.8015) -> (10.7, -90.8015)
  line L9 (13.7, -73.6015) -> (13.7, -87.8015)
  line L10 (18.7, -73.6015) -> (13.7, -73.6015)
  line L11 (18.7, -71.2015) -> (18.7, -73.6015)
  line L12 (13.7, -71.2015) -> (18.7, -71.2015)
  line L13 (13.7, -66.8015) -> (13.7, -71.2015)
  line L14 (-8.7, -66.8015) -> (13.7, -66.8015)
  line L15 (-8.7, -71.2015) -> (-8.7, -66.8015)
  line L16 (-13.7, -71.2015) -> (-8.7, -71.2015)
  line L17 (-13.7, -73.6015) -> (-13.7, -71.2015)
  line L18 (-8.7, -73.6015) -> (-13.7, -73.6015)
  line L19 (-8.7, -90.8015) -> (-8.7, -73.6015)
  line L20 (10.7, -90.8015) -> (-8.7, -90.8015)
  line L21 (14.2, -22) -> (14.2, -89)
  line L22 (14.2, -33.0015) -> (-9, -33.0015)
  line L23 (14.2, -73.6015) -> (18.7, -73.6015)
  line L24 (14.2, -83.6015) -> (14.2, -73.6015)
  line L25 (18.7, -83.6015) -> (14.2, -83.6015)
  line L26 (18.7, -73.6015) -> (18.7, -83.6015)
  point P6 (-13.7, -51.8015)
  point P5 (-9, -30.0015)
  point P10 (-9, -30.0015)
  point P27 (14.2, -33.0015)
  point P15 (18.7, -73.6015)
  point P28 (18.7, -73.6015)
  point P11 (-9, -33.0015)
  point P31 (18.7, -83.6015)
  midpoint L1 P6
  perpendicular L1 L5
  coincident P5 P10
  perpendicular L4 L7
  perpendicular L10 L21
  coincident L21 P27
  perpendicular L21 L22
  horizontal L23
  vertical L24
  horizontal L25
  vertical L26
  coincident P15 P28
  dimension "d655" = -12
  dimension "d656" distance P10 P11 = 3
  dimension "d657" distance L9 L21 = 0.5
  dimension "d658" distance P28 P31 = 10
extrude "Extrude126" add sketch "Sketch103" profile of L1 L3 L4 L6 L7 L10 L21 L22 L23 L24 L25 L26 against normal blind 14.6
sketch "Sketch104" plane through (0, 0, 6.6) normal (0, 0, 1) x axis (1, 0, 0)
  line L1 (-13.7, -73.6015) -> (-13.7, -30.0015)
  line L2 (-9, -73.6015) -> (-13.7, -73.6015)
  line L3 (-9, -39.8015) -> (-9, -73.6015)
  line L4 (14.2, -39.8015) -> (-9, -39.8015)
  line L5 (14.2, -33.0015) -> (14.2, -39.8015)
  line L6 (-9, -33.0015) -> (14.2, -33.0015)
  line L7 (-9, -30.0015) -> (-9, -33.0015)
  line L8 (-13.7, -30.0015) -> (-9, -30.0015)
  line L9 (-13.7, -39.8015) -> (14.2, -39.8015)
  line L10 (-13.7, -30.0015) -> (-13.7, -39.8015)
  line L11 (14.2, -30.0015) -> (-13.7, -30.0015)
  line L12 (14.2, -39.8015) -> (14.2, -30.0015)
  point P2 (-13.7, -30.0015)
  point P12 (-13.7, -30.0015)
  point P6 (14.2, -39.8015)
  point P10 (14.2, -39.8015)
  horizontal L9
  vertical L10
  horizontal L11
  vertical L12
  coincident P2 P12
  coincident P6 P10
extrude "Extrude127" add sketch "Sketch104" profile of L1 L4 L5 L6 L7 L8 L9 L10 L11 L12 along normal blind 12.4
extrude "Extrude128" add of existing geometry blind 12.4
sketch "Sketch105" plane through (0, -39.8015, 0) normal (0, -1, 0) x axis (1, 0, 0)
  line L1 (9, -8) -> (9, -2.3714)
  line L2 (14.2, -8) -> (9, -8)
  line L3 (14.2, 19) -> (14.2, -8)
  line L4 (-13.7, 19) -> (14.2, 19)
  line L5 (-13.7, 6.6) -> (-13.7, 19)
  line L6 (-9, 6.6) -> (-13.7, 6.6)
  line L7 (-9, -2.3714) -> (-9, 6.6)
  line L8 (-6.9285, -2.3714) -> (-9, -2.3714)
  line L9 (-5.6202, -2.3714) -> (-6.9285, -2.3714)
  line L10 (3, -5.1) -> (-3, -5.1)
  line L11 (6.9285, -2.3714) -> (5.6202, -2.3714)
  line L12 (9, -2.3714) -> (6.9285, -2.3714)
  arc A1 centre (0, 0) radius 6.1 clockwise from (-3.66, -4.88) to (-5.6202, -2.3714)
  arc A2 centre (-3, -4) radius 1.1 clockwise from (-3, -5.1) to (-3.66, -4.88)
  arc A3 centre (3, -4) radius 1.1 clockwise from (3.66, -4.88) to (3, -5.1)
  arc A4 centre (0, 0) radius 6.1 clockwise from (5.6202, -2.3714) to (3.66, -4.88)
  circle C1 centre (7.95, 12.8) radius 1.25
  circle C2 centre (7.95, 12.8) radius 1.25
  concentric C1 C2
  dimension "d665" diameter C2 = 2.5
extrude "Extrude129" cut sketch "Sketch105" profile of C1 C2 against normal blind 6.8
fillet "Fillet12" radius 7.5
sketch "Sketch106" plane through (0, 0, -8) normal (0, 0, 1) x axis (1, 0, 0)
  line L1 (18.7, -73.6015) -> (14.2, -73.6015)
  line L2 (18.7, -83.6015) -> (18.7, -73.6015)
  line L3 (14.2, -83.6015) -> (18.7, -83.6015)
  line L4 (14.2, -73.6015) -> (14.2, -83.6015)
  line L5 (9, -90.8015) -> (9, -71.8015)
  line L6 (49, -90.8015) -> (9, -90.8015)
  line L7 (49, -71.8015) -> (49, -90.8015)
  line L8 (9, -71.8015) -> (49, -71.8015)
  line L9 (13.7, -87.8015) -> (10.7, -90.8015)
  line L10 (13.7, -73.6015) -> (13.7, -87.8015)
  line L11 (18.7, -73.6015) -> (13.7, -73.6015)
  line L12 (18.7, -71.2015) -> (18.7, -73.6015)
  line L13 (13.7, -71.2015) -> (18.7, -71.2015)
  line L14 (13.7, -66.8015) -> (13.7, -71.2015)
  line L15 (-8.7, -66.8015) -> (13.7, -66.8015)
  line L16 (-8.7, -71.2015) -> (-8.7, -66.8015)
  line L17 (-13.7, -71.2015) -> (-8.7, -71.2015)
  line L18 (-13.7, -73.6015) -> (-13.7, -71.2015)
  line L19 (-8.7, -73.6015) -> (-13.7, -73.6015)
  line L20 (-8.7, -90.8015) -> (-8.7, -73.6015)
  line L21 (10.7, -90.8015) -> (-8.7, -90.8015)
  line L22 (18.7, -73.6015) -> (18.7, -83.6015)
  line L23 (14.2, -73.6015) -> (18.7, -73.6015)
  line L24 (14.2, -83.6015) -> (14.2, -73.6015)
  line L25 (18.7, -83.6015) -> (14.2, -83.6015)
  line L26 (9, -83.6015) -> (14.2, -83.6015)
  line L27 (9, -71.8015) -> (9, -39.8015)
  line L28 (9, -12.8015) -> (9, -71.8015)
  line L29 (9, -16.3015) -> (9, -12.8015)
  line L30 (9, -25.8015) -> (9, -16.3015)
  line L31 (9, -33.0015) -> (9, -25.8015)
  line L32 (9, -39.8015) -> (9, -33.0015)
  line L33 (9, -71.8015) -> (9, -90.8015)
  line L34 (9, -77.8015) -> (9, -71.8015)
  line L35 (9, -87.3015) -> (9, -77.8015)
  line L36 (9, -90.8015) -> (9, -87.3015)
  point P5 (14.2, -83.6015)
  point P27 (14.2, -83.6015)
  point P28 (9, -83.6015)
  coincident P5 P27
  coincident L5 P28
  perpendicular L5 L26
extrude "Extrude130" add sketch "Sketch106" profile of L1 L4 L5 L8 L10 L11 L12 L13 L14 L15 L23 L24 L26 L27 L28 L33 L34 L35 along normal blind 14.6
sketch "Sketch107" plane through (0, -83.6015, 0) normal (0, -1, 0) x axis (1, 0, 0)
  line L1 (18.7, -8) -> (9, -8)
  line L2 (18.7, 19) -> (18.7, -8)
  line L3 (14.2, 19) -> (18.7, 19)
  line L4 (14.2, 6.6) -> (14.2, 19)
  line L5 (9, 6.6) -> (14.2, 6.6)
  line L6 (9, -2.3714) -> (9, 6.6)
  line L7 (9, -8) -> (9, -2.3714)
  line L8 (15.4862, 6.6) -> (14.2, 6.6)
  line L9 (18.7, 6.6) -> (15.4862, 6.6)
  point P6 (14.2, 6.6)
  point P9 (14.2, 6.6)
  point P11 (18.7, 6.6)
  coincident P6 P9
  coincident L2 P11
  perpendicular L2 L9
extrude "Extrude131" add sketch "Sketch107" profile of L1 L2 L5 L6 L7 L8 L9 along normal blind 7.2
sketch "Sketch108" plane through (0, -73.6015, 0) normal (0, 1, 0) x axis (-1, 0, 0)
  line L1 (-14.2, 6.6) -> (-18.7, 6.6)
  line L2 (-14.2, 19) -> (-14.2, 6.6)
  line L3 (-18.7, 19) -> (-14.2, 19)
  line L4 (-18.7, 6.6) -> (-18.7, 19)
  line L5 (8.7, 6.6) -> (8.7, 19)
  line L6 (13.7, 6.6) -> (8.7, 6.6)
  line L7 (13.7, 12.2) -> (13.7, 6.6)
  line L8 (12.5533, 12.2) -> (13.7, 12.2)
  line L9 (13.7, 13.4) -> (12.5533, 13.4)
  line L10 (13.7, 19) -> (13.7, 13.4)
  line L11 (8.7, 19) -> (13.7, 19)
  line L12 (-18.7, 19) -> (-13.7, 19)
  line L13 (-18.7, 13.4) -> (-18.7, 19)
  line L14 (-17.5533, 13.4) -> (-18.7, 13.4)
  line L15 (-18.7, 12.2) -> (-17.5533, 12.2)
  line L16 (-18.7, 6.6) -> (-18.7, 12.2)
  line L17 (-13.7, 6.6) -> (-18.7, 6.6)
  line L18 (-13.7, 19) -> (-13.7, 6.6)
  arc A1 centre (11.4, 12.8) radius 1.3 clockwise from (12.5533, 12.2) to (12.5533, 13.4)
  arc A2 centre (-16.4, 12.8) radius 1.3 clockwise from (-17.5533, 13.4) to (-17.5533, 12.2)
  circle C1 centre (-16.4, 12.8) radius 0.75
  circle C2 centre (11.4, 12.8) radius 1
  circle C3 centre (-16.4, 12.8) radius 1
  concentric A2 C1
  concentric A1 C2
  concentric C1 C3
  dimension "d674" diameter C1 = 1.5
  dimension "d675" diameter C2 = 2
  dimension "d676" diameter C3 = 2
extrude "Extrude132" cut sketch "Sketch108" profile of C1 C2 C3 against normal blind 12
sketch "Sketch109" plane through (9, 0, 0) normal (1, 0, 0) x axis (0, 0, -1)
  line L1 (8, -66.8015) -> (2.3714, -66.8015)
  line L2 (8, -71.8015) -> (8, -66.8015)
  line L3 (8.0004, -71.8015) -> (8, -71.8015)
  line L4 (8.0004, -12.8015) -> (8.0004, -71.8015)
  line L5 (2.3714, -12.8015) -> (8.0004, -12.8015)
  line L6 (2.3714, -16.3015) -> (2.3714, -12.8015)
  line L7 (2.3714, -25.8015) -> (2.3714, -16.3015)
  line L8 (2.3714, -33.0015) -> (2.3714, -25.8015)
  line L9 (8, -33.0015) -> (2.3714, -33.0015)
  line L10 (8, -39.8015) -> (8, -33.0015)
  line L11 (2.3714, -39.8015) -> (8, -39.8015)
  line L12 (2.3714, -66.8015) -> (2.3714, -39.8015)
extrude "Extrude133" cut of existing geometry blind -8.6
sketch "Sketch110" plane through (0, -12.8015, 0) normal (0, -1, 0) x axis (1, 0, 0)
  line L1 (7.467, -2.3714) -> (6.6499, -4.414)
  line L2 (9, -2.3714) -> (7.467, -2.3714)
  line L3 (9, -8.0004) -> (9, -2.3714)
  line L4 (49, -8.0004) -> (9, -8.0004)
  line L5 (49, 5) -> (49, -8.0004)
  line L6 (6.05, 5) -> (49, 5)
  line L7 (6.05, -5.05) -> (6.05, 5)
  line L8 (4.5768, -5.05) -> (6.05, -5.05)
  line L9 (-0.6148, -7) -> (0.6148, -7)
  line L10 (-6.05, -5.05) -> (-4.5768, -5.05)
  line L11 (-6.05, 19) -> (-6.05, -5.05)
  line L12 (-9, 19) -> (-6.05, 19)
  line L13 (-9, -2.3714) -> (-9, 19)
  line L14 (-7.467, -2.3714) -> (-9, -2.3714)
  line L15 (-6.6499, -4.414) -> (-7.467, -2.3714)
  line L16 (-4.4315, -13) -> (-4.4315, -7.2615)
  line L17 (4.4315, -13) -> (-4.4315, -13)
  line L18 (4.4315, -7.2615) -> (4.4315, -13)
  line L19 (9, 5) -> (9, -8.0004)
  arc A1 centre (0.6148, -2) radius 6.5 clockwise from (6.6499, -4.414) to (4.4315, -7.2615)
  arc A2 centre (0.6148, -2) radius 5 clockwise from (4.5768, -5.05) to (0.6148, -7)
  arc A3 centre (-0.6148, -2) radius 5 clockwise from (-0.6148, -7) to (-4.5768, -5.05)
  arc A4 centre (-0.6148, -2) radius 6.5 clockwise from (-4.4315, -7.2615) to (-6.6499, -4.414)
  point P7 (9, -8.0004)
  point P26 (9, -8.0004)
  point P27 (9, 5)
  coincident P7 P26
  coincident L6 P27
  perpendicular L6 L19
extrude "Extrude134" cut sketch "Sketch110" profile of L3 L4 L5 L6 L19 against normal blind 8.6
